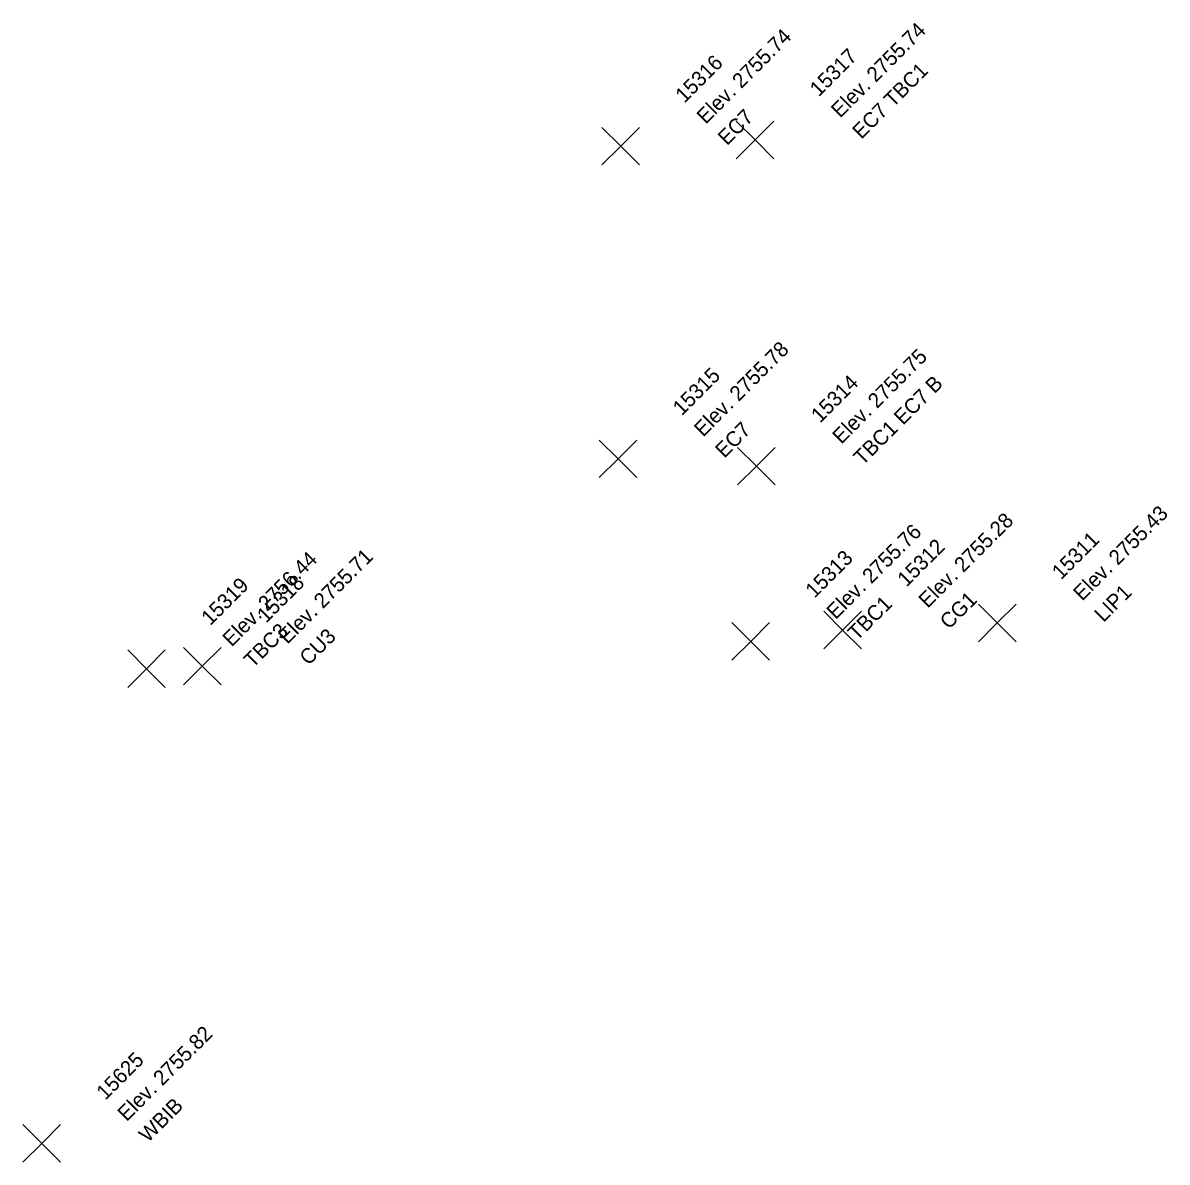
# Model space of a CAD drawing. Extents: x 2493999 to 2503109, y 700767 to 706646.
# Drawn here: x 2502254 to 2502263.14, y 703571.67 to 703580.77 of the extents above; entities that cross this region are included whole.
import ezdxf

# ---------------------------------------------------------------- set-up
doc = ezdxf.new("R2010")
doc.units = 0
doc.layers.add('ALG_CL_BLUE_Horiz', color=7, linetype='Continuous')
doc.layers.add('DES_SURFACE_Existing-Ground', color=7, linetype='Continuous')

msp = doc.modelspace()

# ---------------------------------------------------------------- linework, layer by layer
at = {"layer": 'ALG_CL_BLUE_Horiz'}
for points in [[(2502259.849, 703579.832), (2502259.699, 703579.982), (2502259.849, 703579.832), (2502259.699, 703579.682), (2502259.849, 703579.832), (2502259.999, 703579.682), (2502259.849, 703579.832), (2502259.999, 703579.982)], [(2502258.776, 703579.782), (2502258.626, 703579.932), (2502258.776, 703579.782), (2502258.626, 703579.632), (2502258.776, 703579.782), (2502258.926, 703579.632), (2502258.776, 703579.782), (2502258.926, 703579.932)], [(2502258.755, 703577.285), (2502258.605, 703577.435), (2502258.755, 703577.285), (2502258.605, 703577.135), (2502258.755, 703577.285), (2502258.905, 703577.135), (2502258.755, 703577.285), (2502258.905, 703577.435)], [(2502259.859, 703577.227), (2502259.709, 703577.377), (2502259.859, 703577.227), (2502259.709, 703577.077), (2502259.859, 703577.227), (2502260.009, 703577.077), (2502259.859, 703577.227), (2502260.009, 703577.377)], [(2502260.548, 703575.918), (2502260.398, 703576.068), (2502260.548, 703575.918), (2502260.398, 703575.768), (2502260.548, 703575.918), (2502260.698, 703575.768), (2502260.548, 703575.918), (2502260.698, 703576.068)], [(2502261.782, 703575.975), (2502261.632, 703576.125), (2502261.782, 703575.975), (2502261.632, 703575.825), (2502261.782, 703575.975), (2502261.932, 703575.825), (2502261.782, 703575.975), (2502261.932, 703576.125)], [(2502259.814, 703575.828), (2502259.664, 703575.978), (2502259.814, 703575.828), (2502259.664, 703575.678), (2502259.814, 703575.828), (2502259.964, 703575.678), (2502259.814, 703575.828), (2502259.964, 703575.978)], [(2502255.436, 703575.63), (2502255.286, 703575.78), (2502255.436, 703575.63), (2502255.286, 703575.48), (2502255.436, 703575.63), (2502255.586, 703575.48), (2502255.436, 703575.63), (2502255.586, 703575.78)], [(2502254.991, 703575.609), (2502254.841, 703575.759), (2502254.991, 703575.609), (2502254.841, 703575.459), (2502254.991, 703575.609), (2502255.141, 703575.459), (2502254.991, 703575.609), (2502255.141, 703575.759)], [(2502254.154, 703571.82), (2502254.004, 703571.97), (2502254.154, 703571.82), (2502254.004, 703571.67), (2502254.154, 703571.82), (2502254.304, 703571.67), (2502254.154, 703571.82), (2502254.304, 703571.97)]]:
    msp.add_lwpolyline(points, dxfattribs=at)

# ---------------------------------------------------------------- texts
at = {"layer": 'DES_SURFACE_Existing-Ground'}
for s, p in [('Elev. 2755.74', (2502259.4548, 703579.9517)), ('Elev. 2755.74', (2502260.5278, 703580.0017)), ('15316', (2502259.2851, 703580.1214)), ('15317', (2502260.3581, 703580.1714)), ('EC7 TBC1', (2502260.6975, 703579.832)), ('EC7', (2502259.6245, 703579.782)), ('Elev. 2755.78', (2502259.4338, 703577.4547)), ('Elev. 2755.75', (2502260.5378, 703577.3967)), ('15315', (2502259.2641, 703577.6244)), ('15314', (2502260.3681, 703577.5664)), ('TBC1 EC7 B', (2502260.7075, 703577.227)), ('EC7', (2502259.6035, 703577.285)), ('Elev. 2755.43', (2502262.4608, 703576.1447)), ('Elev. 2755.76', (2502260.4928, 703575.9977)), ('Elev. 2755.28', (2502261.2268, 703576.0877)), ('15311', (2502262.2911, 703576.3144)), ('15312', (2502261.0571, 703576.2574)), ('Elev. 2756.44', (2502255.6698, 703575.7787)), ('Elev. 2755.71', (2502256.1148, 703575.7997)), ('15313', (2502260.3231, 703576.1674)), ('15319', (2502255.5001, 703575.9484)), ('15318', (2502255.9451, 703575.9694)), ('LIP1', (2502262.6305, 703575.975)), ('TBC1', (2502260.6625, 703575.828)), ('CG1', (2502261.3965, 703575.918)), ('TBC3', (2502255.8395, 703575.609)), ('CU3', (2502256.2845, 703575.63)), ('Elev. 2755.82', (2502254.8328, 703571.9897)), ('15625', (2502254.6631, 703572.1594)), ('WBIB', (2502255.0025, 703571.82))]:
    msp.add_text(s, height=0.12, rotation=45, dxfattribs=at).set_placement(p)

doc.saveas('drawing.dxf')
